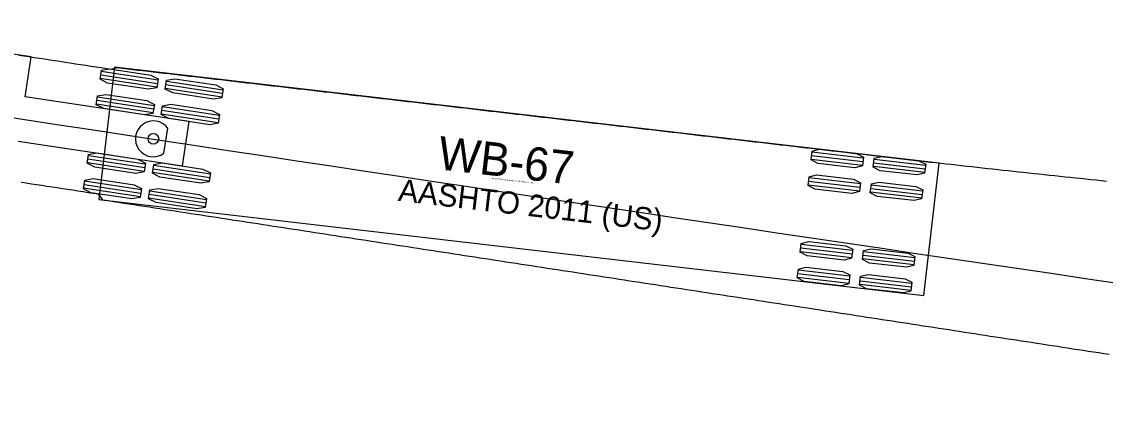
# Model space of a CAD drawing. Extents: x 2175591 to 2194071, y 76570 to 86955.
# Drawn here: x 2192687.6 to 2192756.8, y 86769.9 to 86795.2 of the extents above; entities that cross this region are included whole.
import ezdxf

# ---------------------------------------------------------------- set-up
doc = ezdxf.new("R2010")
doc.units = 0
doc.layers.add('-NOPLT', color=7, linetype='Continuous')

msp = doc.modelspace()

# ---------------------------------------------------------------- linework, layer by layer
at = {"layer": '-NOPLT'}
for p, q in [((2192688.2, 86792.956), (2192673.37, 86795.207)), ((2192687.815, 86790.418), (2192688.2, 86792.956)), ((2192693.514, 86792.293), (2192692.533, 86783.85)), ((2192692.681, 86792.044), (2192696.306, 86791.494)), ((2192746.16, 86786.177), (2192693.514, 86792.293)), ((2192692.612, 86791.591), (2192696.237, 86791.04)), ((2192692.647, 86791.817), (2192696.272, 86791.267)), ((2192696.833, 86791.414), (2192700.459, 86790.863)), ((2192696.765, 86790.96), (2192700.39, 86790.41)), ((2192696.799, 86791.187), (2192700.424, 86790.637)), ((2192698.295, 86788.827), (2192687.815, 86790.418)), ((2192692.365, 86789.959), (2192695.99, 86789.409)), ((2192692.399, 86790.186), (2192696.024, 86789.636)), ((2192692.433, 86790.413), (2192696.058, 86789.862)), ((2192696.517, 86789.329), (2192700.142, 86788.779)), ((2192696.551, 86789.556), (2192700.177, 86789.005)), ((2192696.586, 86789.782), (2192700.211, 86789.232)), ((2192697.865, 86785.993), (2192698.295, 86788.827)), ((2192696.682, 86786.805), (2192696.924, 86788.403)), ((2192687.385, 86787.584), (2192697.865, 86785.993)), ((2192691.831, 86786.445), (2192695.456, 86785.895)), ((2192691.866, 86786.672), (2192695.491, 86786.122)), ((2192737.985, 86786.435), (2192741.263, 86786.054)), ((2192738.012, 86786.662), (2192741.29, 86786.281)), ((2192738.038, 86786.89), (2192741.316, 86786.509)), ((2192742.012, 86786.428), (2192745.289, 86786.047)), ((2192691.797, 86786.219), (2192695.422, 86785.669)), ((2192695.984, 86785.815), (2192699.609, 86785.265)), ((2192696.018, 86786.042), (2192699.643, 86785.492)), ((2192741.959, 86785.973), (2192745.237, 86785.592)), ((2192741.985, 86786.201), (2192745.263, 86785.82)), ((2192745.179, 86777.734), (2192746.16, 86786.177)), ((2192691.618, 86785.041), (2192695.243, 86784.491)), ((2192695.949, 86785.589), (2192699.574, 86785.038)), ((2192737.821, 86785.023), (2192741.099, 86784.642)), ((2192737.848, 86785.251), (2192741.126, 86784.87)), ((2192691.549, 86784.588), (2192695.174, 86784.037)), ((2192691.584, 86784.814), (2192695.209, 86784.264)), ((2192695.77, 86784.41), (2192699.396, 86783.86)), ((2192737.795, 86784.796), (2192741.073, 86784.415)), ((2192741.768, 86784.334), (2192745.046, 86783.953)), ((2192741.795, 86784.562), (2192745.073, 86784.181)), ((2192741.821, 86784.789), (2192745.099, 86784.408)), ((2192692.533, 86783.85), (2192745.179, 86777.734)), ((2192692.533, 86783.85), (2192692.533, 86783.85)), ((2192695.702, 86783.957), (2192699.327, 86783.407)), ((2192695.736, 86784.184), (2192699.361, 86783.634)), ((2192737.354, 86780.996), (2192740.631, 86780.615)), ((2192737.301, 86780.541), (2192740.579, 86780.16)), ((2192737.327, 86780.769), (2192740.605, 86780.388)), ((2192741.3, 86780.307), (2192744.578, 86779.926)), ((2192741.327, 86780.535), (2192744.605, 86780.154)), ((2192741.274, 86780.079), (2192744.552, 86779.698)), ((2192737.11, 86778.902), (2192740.388, 86778.521)), ((2192737.137, 86779.13), (2192740.415, 86778.749)), ((2192737.163, 86779.357), (2192740.441, 86778.976)), ((2192741.136, 86778.896), (2192744.414, 86778.515)), ((2192741.084, 86778.44), (2192744.361, 86778.059)), ((2192741.11, 86778.668), (2192744.388, 86778.287))]:
    msp.add_line(p, q, dxfattribs=at)
for points in [[(2192687.415, 86793.075), (2192687.743, 86793.025), (2192688.072, 86792.975), (2192688.401, 86792.925), (2192688.73, 86792.875), (2192689.058, 86792.825), (2192689.387, 86792.775), (2192689.716, 86792.725), (2192690.045, 86792.675), (2192690.374, 86792.625), (2192690.702, 86792.575), (2192691.031, 86792.524), (2192691.36, 86792.474), (2192691.689, 86792.424), (2192692.018, 86792.374), (2192692.347, 86792.324), (2192692.676, 86792.274), (2192693.006, 86792.224)], [(2192693.006, 86792.224), (2192693.335, 86792.174), (2192693.686, 86792.273), (2192694.017, 86792.235), (2192694.348, 86792.196), (2192694.678, 86792.158), (2192695.009, 86792.12), (2192695.34, 86792.081), (2192695.672, 86792.043), (2192696.003, 86792.004), (2192696.334, 86791.966), (2192696.665, 86791.927), (2192696.996, 86791.889), (2192697.327, 86791.85), (2192697.658, 86791.812), (2192697.989, 86791.773), (2192698.32, 86791.735), (2192698.652, 86791.696), (2192698.983, 86791.658), (2192699.314, 86791.619), (2192699.645, 86791.581), (2192699.976, 86791.543), (2192700.308, 86791.504), (2192700.639, 86791.466), (2192700.97, 86791.427), (2192701.301, 86791.389), (2192701.633, 86791.35), (2192701.964, 86791.312), (2192702.295, 86791.273), (2192702.626, 86791.235), (2192702.958, 86791.196), (2192703.289, 86791.158), (2192703.62, 86791.119), (2192703.952, 86791.081), (2192704.283, 86791.042), (2192704.614, 86791.004), (2192704.945, 86790.965), (2192705.277, 86790.927), (2192705.608, 86790.888), (2192705.939, 86790.85), (2192706.271, 86790.811), (2192706.602, 86790.773), (2192706.933, 86790.734), (2192707.264, 86790.696), (2192707.596, 86790.657), (2192707.927, 86790.619), (2192708.258, 86790.58), (2192708.59, 86790.542), (2192708.921, 86790.503), (2192709.252, 86790.465), (2192709.583, 86790.426), (2192709.914, 86790.388), (2192710.246, 86790.349), (2192710.577, 86790.311), (2192710.908, 86790.273), (2192711.239, 86790.234), (2192711.57, 86790.196), (2192711.901, 86790.157), (2192712.233, 86790.119), (2192712.564, 86790.08), (2192712.895, 86790.042), (2192713.226, 86790.003), (2192713.557, 86789.965), (2192713.888, 86789.926), (2192714.219, 86789.888), (2192714.551, 86789.849), (2192714.882, 86789.811), (2192715.213, 86789.772), (2192715.544, 86789.734), (2192715.875, 86789.695), (2192716.206, 86789.657), (2192716.537, 86789.619), (2192716.868, 86789.58), (2192717.199, 86789.542), (2192717.53, 86789.503), (2192717.861, 86789.465), (2192718.192, 86789.426), (2192718.523, 86789.388), (2192718.854, 86789.349), (2192719.185, 86789.311), (2192719.516, 86789.272), (2192719.847, 86789.234), (2192720.178, 86789.196), (2192720.509, 86789.157), (2192720.84, 86789.119), (2192721.171, 86789.08), (2192721.502, 86789.042), (2192721.833, 86789.003), (2192722.164, 86788.965), (2192722.495, 86788.926), (2192722.825, 86788.888), (2192723.156, 86788.85), (2192723.487, 86788.811), (2192723.818, 86788.773), (2192724.149, 86788.734), (2192724.479, 86788.696), (2192724.81, 86788.657), (2192725.141, 86788.619), (2192725.471, 86788.581), (2192725.802, 86788.542), (2192726.132, 86788.504), (2192726.463, 86788.465), (2192726.793, 86788.427), (2192727.124, 86788.389), (2192727.454, 86788.35), (2192727.785, 86788.312), (2192728.115, 86788.273), (2192728.446, 86788.235), (2192728.776, 86788.197), (2192729.106, 86788.158), (2192729.437, 86788.12), (2192729.767, 86788.082), (2192730.097, 86788.043), (2192730.427, 86788.005), (2192730.758, 86787.966), (2192731.088, 86787.928), (2192731.418, 86787.89), (2192731.748, 86787.851), (2192732.078, 86787.813), (2192732.408, 86787.775), (2192732.739, 86787.736), (2192733.069, 86787.698), (2192733.399, 86787.66), (2192733.729, 86787.621), (2192734.059, 86787.583), (2192734.389, 86787.545), (2192734.719, 86787.506), (2192735.049, 86787.468), (2192735.379, 86787.43), (2192735.709, 86787.391), (2192736.039, 86787.353), (2192736.369, 86787.315), (2192736.699, 86787.276), (2192737.028, 86787.238), (2192737.358, 86787.2), (2192737.688, 86787.161), (2192738.018, 86787.123), (2192738.348, 86787.085), (2192738.678, 86787.046), (2192739.008, 86787.008), (2192739.338, 86786.97), (2192739.667, 86786.931), (2192739.997, 86786.893), (2192740.327, 86786.855), (2192740.657, 86786.816), (2192740.987, 86786.778), (2192741.317, 86786.74), (2192741.646, 86786.701), (2192741.976, 86786.663), (2192742.306, 86786.625), (2192742.636, 86786.587), (2192742.965, 86786.549), (2192743.295, 86786.511), (2192743.625, 86786.473), (2192743.955, 86786.435), (2192744.285, 86786.397), (2192744.614, 86786.36), (2192744.944, 86786.322), (2192745.274, 86786.285), (2192745.604, 86786.247), (2192745.934, 86786.21), (2192746.264, 86786.173), (2192746.594, 86786.136), (2192746.924, 86786.099), (2192747.253, 86786.062), (2192747.583, 86786.025), (2192747.913, 86785.988), (2192748.244, 86785.952), (2192748.574, 86785.915), (2192748.904, 86785.879), (2192749.234, 86785.842), (2192749.564, 86785.806), (2192749.894, 86785.77), (2192750.224, 86785.734), (2192750.555, 86785.698), (2192750.885, 86785.662), (2192751.215, 86785.626), (2192751.546, 86785.591), (2192751.876, 86785.555), (2192752.207, 86785.52), (2192752.537, 86785.484), (2192752.868, 86785.449), (2192753.198, 86785.414), (2192753.529, 86785.379), (2192753.859, 86785.344), (2192754.19, 86785.309), (2192754.521, 86785.274), (2192754.852, 86785.24), (2192755.182, 86785.205), (2192755.513, 86785.171), (2192755.844, 86785.136), (2192756.175, 86785.102), (2192756.506, 86785.068), (2192756.837, 86785.034)], [(2192756.997, 86773.952), (2192756.667, 86774.003), (2192756.337, 86774.054), (2192756.007, 86774.105), (2192755.677, 86774.155), (2192755.348, 86774.206), (2192755.018, 86774.257), (2192754.688, 86774.307), (2192754.358, 86774.358), (2192754.029, 86774.409), (2192753.699, 86774.459), (2192753.37, 86774.51), (2192753.04, 86774.561), (2192752.71, 86774.611), (2192752.381, 86774.662), (2192752.052, 86774.713), (2192751.722, 86774.763), (2192751.393, 86774.814), (2192751.063, 86774.865), (2192750.734, 86774.915), (2192750.405, 86774.966), (2192750.076, 86775.016), (2192749.746, 86775.067), (2192749.417, 86775.117), (2192749.088, 86775.168), (2192748.759, 86775.219), (2192748.43, 86775.269), (2192748.101, 86775.32), (2192747.772, 86775.37), (2192747.443, 86775.421), (2192747.114, 86775.471), (2192746.785, 86775.522), (2192746.456, 86775.572), (2192746.127, 86775.623), (2192745.798, 86775.673), (2192745.47, 86775.724), (2192745.141, 86775.774), (2192744.812, 86775.825), (2192744.483, 86775.875), (2192744.155, 86775.926), (2192743.826, 86775.976), (2192743.497, 86776.026), (2192743.169, 86776.077), (2192742.84, 86776.127), (2192742.511, 86776.178), (2192742.183, 86776.228), (2192741.854, 86776.279), (2192741.526, 86776.329), (2192741.197, 86776.379), (2192740.869, 86776.43), (2192740.54, 86776.48), (2192740.212, 86776.531), (2192739.883, 86776.581), (2192739.554, 86776.632), (2192739.226, 86776.682), (2192738.897, 86776.732), (2192738.569, 86776.783), (2192738.24, 86776.833), (2192737.912, 86776.884), (2192737.583, 86776.934), (2192737.255, 86776.984), (2192736.926, 86777.035), (2192736.598, 86777.085), (2192736.269, 86777.136), (2192735.94, 86777.186), (2192735.612, 86777.236), (2192735.283, 86777.287), (2192734.954, 86777.337), (2192734.626, 86777.388), (2192734.297, 86777.438), (2192733.968, 86777.488), (2192733.64, 86777.539), (2192733.311, 86777.589), (2192732.982, 86777.64), (2192732.654, 86777.69), (2192732.325, 86777.74), (2192731.996, 86777.791), (2192731.667, 86777.841), (2192731.338, 86777.892), (2192731.009, 86777.942), (2192730.68, 86777.993), (2192730.351, 86778.043), (2192730.022, 86778.093), (2192729.693, 86778.144), (2192729.364, 86778.194), (2192729.035, 86778.245), (2192728.706, 86778.295), (2192728.377, 86778.346), (2192728.048, 86778.396), (2192727.719, 86778.447), (2192727.39, 86778.497), (2192727.06, 86778.548), (2192726.731, 86778.598), (2192726.402, 86778.649), (2192726.073, 86778.699), (2192725.743, 86778.75), (2192725.414, 86778.8), (2192725.085, 86778.851), (2192724.755, 86778.901), (2192724.426, 86778.952), (2192724.096, 86779.002), (2192723.767, 86779.053), (2192723.437, 86779.103), (2192723.108, 86779.154), (2192722.778, 86779.204), (2192722.449, 86779.255), (2192722.119, 86779.305), (2192721.79, 86779.356), (2192721.46, 86779.406), (2192721.131, 86779.457), (2192720.801, 86779.507), (2192720.472, 86779.558), (2192720.142, 86779.609), (2192719.813, 86779.659), (2192719.483, 86779.71), (2192719.153, 86779.76), (2192718.824, 86779.811), (2192718.494, 86779.861), (2192718.165, 86779.912), (2192717.835, 86779.962), (2192717.505, 86780.013), (2192717.176, 86780.064), (2192716.846, 86780.114), (2192716.517, 86780.165), (2192716.187, 86780.215), (2192715.857, 86780.266), (2192715.528, 86780.316), (2192715.198, 86780.367), (2192714.869, 86780.418), (2192714.539, 86780.468), (2192714.209, 86780.519), (2192713.88, 86780.569), (2192713.55, 86780.62), (2192713.221, 86780.67), (2192712.891, 86780.721), (2192712.561, 86780.772), (2192712.232, 86780.822), (2192711.902, 86780.873), (2192711.573, 86780.923), (2192711.243, 86780.974), (2192710.914, 86781.024), (2192710.584, 86781.075), (2192710.255, 86781.126), (2192709.925, 86781.176), (2192709.596, 86781.227), (2192709.266, 86781.277), (2192708.937, 86781.328), (2192708.607, 86781.379), (2192708.278, 86781.429), (2192707.948, 86781.48), (2192707.619, 86781.53), (2192707.289, 86781.581), (2192706.96, 86781.632), (2192706.63, 86781.682), (2192706.301, 86781.733), (2192705.972, 86781.783), (2192705.642, 86781.834), (2192705.313, 86781.885), (2192704.983, 86781.935), (2192704.654, 86781.986), (2192704.324, 86782.036), (2192703.995, 86782.087), (2192703.666, 86782.138), (2192703.336, 86782.188), (2192703.007, 86782.239), (2192702.677, 86782.289), (2192702.348, 86782.34), (2192702.019, 86782.391), (2192701.689, 86782.441), (2192701.36, 86782.492), (2192701.03, 86782.543), (2192700.701, 86782.593), (2192700.372, 86782.644), (2192700.042, 86782.695), (2192699.713, 86782.745), (2192699.383, 86782.796), (2192699.054, 86782.847), (2192698.724, 86782.897), (2192698.395, 86782.948), (2192698.065, 86782.999), (2192697.736, 86783.049), (2192697.406, 86783.1), (2192697.077, 86783.151), (2192696.747, 86783.201), (2192696.418, 86783.252), (2192696.088, 86783.303), (2192695.759, 86783.354), (2192695.429, 86783.404), (2192695.1, 86783.455), (2192694.77, 86783.506), (2192694.44, 86783.556), (2192694.111, 86783.607), (2192693.781, 86783.658), (2192693.451, 86783.709), (2192693.122, 86783.759), (2192692.792, 86783.81), (2192692.51, 86784.189), (2192692.18, 86784.239), (2192691.85, 86784.289), (2192691.52, 86784.339), (2192691.19, 86784.39), (2192690.86, 86784.44), (2192690.53, 86784.49), (2192690.2, 86784.54), (2192689.87, 86784.59), (2192689.54, 86784.641), (2192689.21, 86784.691), (2192688.879, 86784.741), (2192688.549, 86784.792), (2192688.219, 86784.842), (2192687.889, 86784.892), (2192687.558, 86784.943)]]:
    msp.add_lwpolyline(points, dxfattribs=at)
for points in [[(2192692.604, 86791.535), (2192692.689, 86792.1), (2192693.223, 86792.193), (2192695.833, 86791.797), (2192696.315, 86791.55), (2192696.229, 86790.984), (2192695.695, 86790.891), (2192693.085, 86791.287)], [(2192696.756, 86790.904), (2192696.842, 86791.47), (2192697.375, 86791.563), (2192699.985, 86791.167), (2192700.467, 86790.92), (2192700.381, 86790.354), (2192699.848, 86790.261), (2192697.238, 86790.657)], [(2192692.356, 86789.903), (2192692.442, 86790.469), (2192692.975, 86790.562), (2192695.585, 86790.166), (2192696.067, 86789.919), (2192695.981, 86789.353), (2192695.448, 86789.26), (2192692.838, 86789.656)], [(2192696.508, 86789.273), (2192696.594, 86789.838), (2192697.128, 86789.932), (2192699.738, 86789.536), (2192700.219, 86789.288), (2192700.134, 86788.723), (2192699.6, 86788.629), (2192696.99, 86789.026)], [(2192737.979, 86786.378), (2192738.045, 86786.946), (2192738.524, 86787.064), (2192740.884, 86786.79), (2192741.323, 86786.566), (2192741.257, 86785.997), (2192740.778, 86785.879), (2192738.418, 86786.154)], [(2192691.788, 86786.163), (2192691.874, 86786.728), (2192692.407, 86786.822), (2192695.018, 86786.425), (2192695.499, 86786.178), (2192695.413, 86785.612), (2192694.88, 86785.519), (2192692.27, 86785.915)], [(2192741.952, 86785.917), (2192742.018, 86786.485), (2192742.497, 86786.603), (2192744.857, 86786.328), (2192745.296, 86786.104), (2192745.23, 86785.536), (2192744.751, 86785.418), (2192742.391, 86785.692)], [(2192695.941, 86785.532), (2192696.027, 86786.098), (2192696.56, 86786.191), (2192699.17, 86785.795), (2192699.652, 86785.548), (2192699.566, 86784.982), (2192699.032, 86784.889), (2192696.422, 86785.285)], [(2192691.541, 86784.531), (2192691.627, 86785.097), (2192692.16, 86785.19), (2192694.77, 86784.794), (2192695.252, 86784.547), (2192695.166, 86783.981), (2192694.632, 86783.888), (2192692.022, 86784.284)], [(2192737.788, 86784.739), (2192737.854, 86785.307), (2192738.333, 86785.425), (2192740.693, 86785.151), (2192741.132, 86784.927), (2192741.066, 86784.358), (2192740.588, 86784.24), (2192738.227, 86784.515)], [(2192741.762, 86784.278), (2192741.828, 86784.846), (2192742.306, 86784.964), (2192744.667, 86784.689), (2192745.106, 86784.465), (2192745.04, 86783.897), (2192744.561, 86783.779), (2192742.201, 86784.053)], [(2192695.693, 86783.901), (2192695.779, 86784.467), (2192696.312, 86784.56), (2192698.922, 86784.164), (2192699.404, 86783.916), (2192699.318, 86783.351), (2192698.785, 86783.258), (2192696.175, 86783.654)], [(2192737.294, 86780.484), (2192737.36, 86781.053), (2192737.839, 86781.171), (2192740.199, 86780.896), (2192740.638, 86780.672), (2192740.572, 86780.104), (2192740.093, 86779.986), (2192737.733, 86780.26)], [(2192741.267, 86780.023), (2192741.333, 86780.591), (2192741.812, 86780.709), (2192744.172, 86780.435), (2192744.611, 86780.21), (2192744.545, 86779.642), (2192744.067, 86779.524), (2192741.706, 86779.798)], [(2192737.104, 86778.845), (2192737.17, 86779.414), (2192737.648, 86779.532), (2192740.009, 86779.257), (2192740.448, 86779.033), (2192740.382, 86778.465), (2192739.903, 86778.347), (2192737.543, 86778.621)], [(2192741.077, 86778.384), (2192741.143, 86778.952), (2192741.622, 86779.07), (2192743.982, 86778.796), (2192744.421, 86778.571), (2192744.355, 86778.003), (2192743.876, 86777.885), (2192741.516, 86778.159)]]:
    msp.add_lwpolyline(points, close=True, dxfattribs=at)
msp.add_circle((2192696.004, 86787.725), 0.34, dxfattribs=at)
for centre, radius, start, end in [((2194674.65, 99822.88), 13184.487, 261.2840472, 261.8994114), ((2192696.004, 86787.725), 1.143, 36.36954, 306.36954)]:
    msp.add_arc(centre, radius, start, end, dxfattribs=at)

# ---------------------------------------------------------------- texts
for s, height, p in [('WB-67', 2.125, (2192714.089, 86785.795)), ('AASHTO 2011 (US)', 1.41667, (2192711.587, 86783.769)), ('(c) 2022 Transoft Solutions, Inc. All rights reserved.', 0.085, (2192717.613, 86785.172))]:
    msp.add_text(s, height=height, rotation=353.37318, dxfattribs=at).set_placement(p)

doc.saveas('drawing.dxf')
